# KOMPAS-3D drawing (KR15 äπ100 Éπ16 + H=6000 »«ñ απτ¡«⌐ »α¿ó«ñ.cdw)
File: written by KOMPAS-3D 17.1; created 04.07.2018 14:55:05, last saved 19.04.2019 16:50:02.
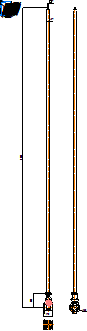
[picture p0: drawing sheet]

Sheet 1: A4, portrait

Title block, sheet 1: name: KR15 Ду100 Ру16 + / H=6000 под ручной привод; material: Внимание! Данный продукт является объектом авторского права ООО «Торговый Дом АДЛ». / Запрещается изменение, копирование, распространение / (в том числе путем копирования на другие сайты и ресурсы в Интернете) / или любое иное использование информации и объектов без предварительного / согласия правообладателя (ООО «Торговый Дом АДЛ»).; mass: 36,7; sheets: 1; organisation: ООО "Торговый дом АДЛ"; sheet format: A4; stored path: \\adlc.lan\data\АДЛ_ПКД\3D-модели\ADL production\Клиновые задвижки серии KR ГРАНАР\Клиновые задвижки KR15 со стационарным удлинением\KOMPAS 2D\KR15 Ду100 Ру16 + H=6000 под ручной привод.cdw

Views: Проекционный вид 6, Проекционный вид 10, Проекционный вид 12, Проекционный вид 13
Referenced files in C:\Users\kka\KOMPAS_Work\Удлинения БИВАЛ ф. ADL\!Задвижки\У_ду_40-100\: Сборка40-100.a3d
Referenced files in C:\Users\kka\KOMPAS_Work\!Trash\ГРАНАР KR Задвижки с приводами и удлинениями\С приводами\: KR15 Ду100 Ру16.m3d
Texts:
  kka
  adl
  Сборка
  Крепежное изделие ГОСТ
  Болт
  ГОСТ
  Гайка
  Лит-Масса-Масштаб
  Материал-Предприятие
  Title Specification
  Body Specification ( left align )
  Body Specificaton ( centered )
  Поз.
  Кол.
  Приме-
  чание
  Таблица спецификации
Dimensions and other numbers on the sheet: 6000; 282; 190; 27; 57; 180; 4; 1; 58; 40Х; 019; 1:1; 36,7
